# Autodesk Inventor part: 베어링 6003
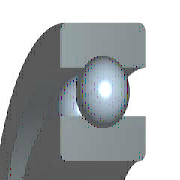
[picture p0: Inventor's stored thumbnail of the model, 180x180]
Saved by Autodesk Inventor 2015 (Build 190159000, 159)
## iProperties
Created: 2012-02
Part Number: 베어링 6003
Material: 강철, 연강
Description: 깊은 그루브 볼 베어링
Document SubType Name: Modeling
Standard: KS B 2023
Designer: mduedu
Standards Organization: KS
Language: ko-KR
Size Designation: 6003 - 17 x 35 x 10
Categories: <MemberInstance><Categories><Category DisplayName="샤프트 부품" InternalName="7f7aeb1f-a693-4053-b835-cee3144e0d98" Mnemonic="SHFT"><Category DisplayName="베어링" Inter
Density: 7.86 g/cm^3
Mass: 39.0276 g
Surface Area: 48.7538 cm^2
Volume: 4.96535 cm^3
Appearance: 노란색
IsCustomPart: 1
Author: mduedu
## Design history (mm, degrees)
sketch "스케치" dims "d0" = 4.68 (= -0.26 x WD + 0.26 x BD)
  geometry: L1 (2.66, 13)-(7.34, 13); L2 (5, 13)-(5, 10.66); L3 (5, 13)-(5, 15.34); L4 (3.261, 11.434)-(0, 11.434); L5 (0, 8.5)-(10, 8.5); L6 (3.261, 14.566)-(0, 14.566); L7 (0, 17.5)-(10, 17.5); L8 (10, 8.5)-(10, 11.434); L9 (6.739, 11.434)-(10, 11.434); L10 (6.739, 14.566)-(10, 14.566); L11 (10, 17.5)-(10, 14.566); L12 (-1.4, 0)-(8.4, 0) reference; L13 (0, -0.3)-(0, 5.3) reference
  constraints: 22 end point, 4 point on line, 2 collinear, 2 perpendicular, 2 symmetric about line, 1 midpoint, 1 parallel, 14 other
  dimensions: "d9" = 17 diameter of L5 L12 (= WD); "d11" = 35 diameter of L7 L12 (= BD); "d12" = 10 distance between parallel lines of L8 L13 (= KB); "d13" = 22.868 diameter of L9 L12 (= 0.326 x BD + 0.674 x WD)
revolve "본체" stored, may be unused: angle "d6" = 90 deg
revolve "볼" stored, may be unused: angle "d7" = 90 deg
pattern_circular "IDS_ARRAYBALL[SIMPL:T]" dims angle "d3" = 360 deg
body "Solid1"
fillet "모깎기1" dims "d1" = 0.3 (= KRS)
other parameters: "WD" = 17 [user parameter; used in 5 equation terms], "BD" = 35 [user parameter; used in 5 equation terms], "KB" = 10 [user parameter; used in 1 equation term], "KRS" = 0.3 [user parameter; used in 1 equation term], "d4" = 0, "d5" = 0, "d8" = 0, "d14" = 0, "d15" = 0, "BBA" = 0 [user parameter], "BC0" = 3250000 [user parameter], "BC" = 6050000 [user parameter], "BR" = 17.5 (= 0.5 x BD) [user parameter], "WR" = 8.5 (= 0.5 x WD) [user parameter]
